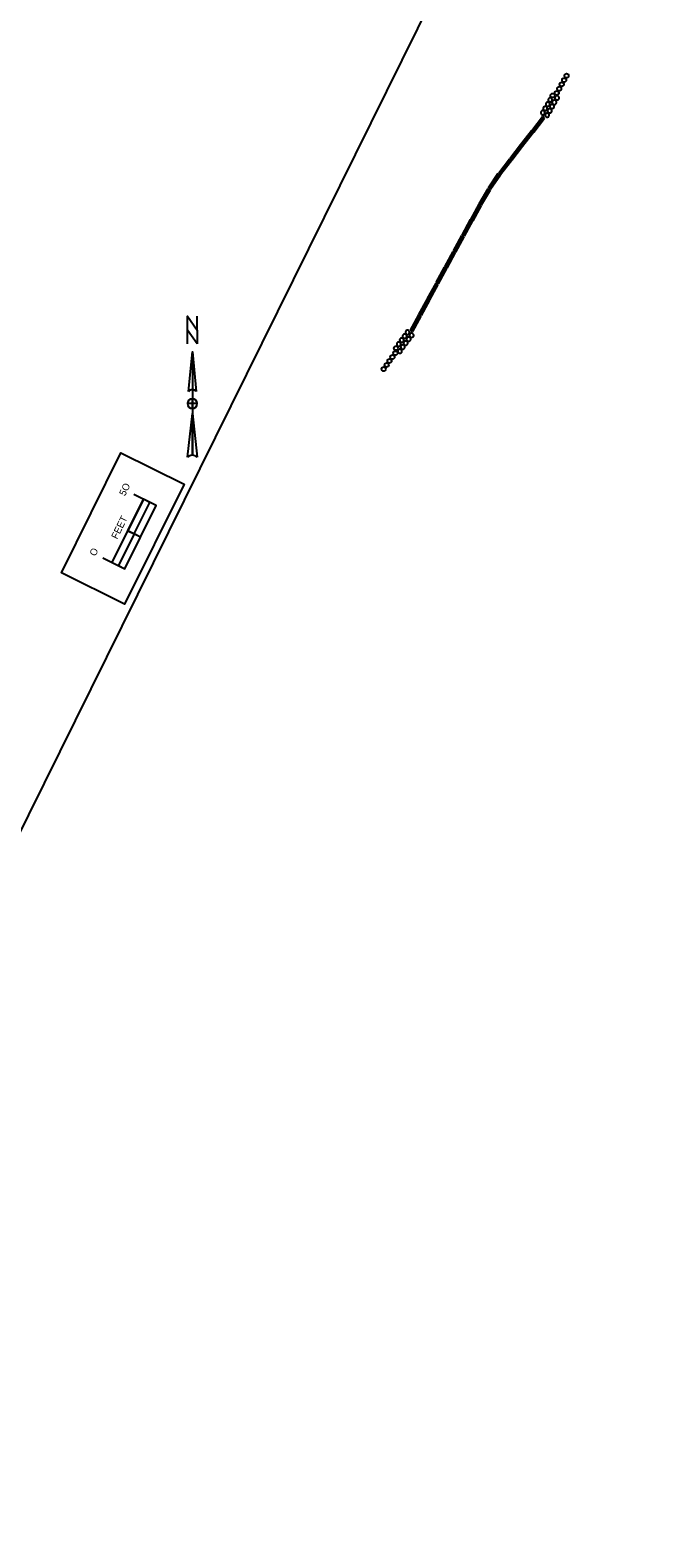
# Model space of a CAD drawing. Extents: x 14104283 to 14120882, y 8635219 to 8671666.
# Drawn here: x 14119252 to 14119692, y 8667406 to 8668475 of the extents above; entities that cross this region are included whole.
import ezdxf

# ---------------------------------------------------------------- set-up
doc = ezdxf.new("R2010")
doc.units = 0
for name, color, linetype in [('DisCLMLORPoints', 7, 'Continuous'), ('dsnBarrierTempUnpinned', 7, 'Continuous'), ('dsnCellsNorthArrow', 7, 'Continuous'), ('dsnCellsScaleBlock', 7, 'Continuous'), ('dsnNonPlotable', 7, 'Continuous')]:
    doc.layers.add(name, color=color, linetype=linetype)

msp = doc.modelspace()

# ---------------------------------------------------------------- linework, layer by layer
at = {"layer": 'DisCLMLORPoints'}
for centre in [(14119630.7, 8668439.8), (14119632.4, 8668442.9), (14119622.5, 8668428.9), (14119622.5, 8668428.9), (14119625.5, 8668430.7), (14119627.2, 8668433.7), (14119629, 8668436.8), (14119511.1, 8668246.2), (14119511.5, 8668249.7), (14119511.5, 8668249.7), (14119504.9, 8668237.8), (14119506.9, 8668240.6), (14119509, 8668243.4), (14119502.8, 8668234.9)]:
    msp.add_circle(centre, 1.5, dxfattribs=at)
for centre, start, end in [((14119617.3, 8668419.7), 55.5784, 235.5784), ((14119617.3, 8668419.7), 235.5784, 55.5784), ((14119619.1, 8668422.8), 55.5784, 235.5784), ((14119619.1, 8668422.8), 235.5784, 55.5784), ((14119620.4, 8668418), 55.5784, 235.5784), ((14119620.8, 8668425.8), 55.5784, 235.5784), ((14119620.4, 8668418), 235.5784, 55.5784), ((14119620.8, 8668425.8), 235.5784, 55.5784), ((14119622.1, 8668421.1), 55.5784, 235.5784), ((14119622.1, 8668421.1), 235.5784, 55.5784), ((14119623.8, 8668424.1), 55.5784, 235.5784), ((14119623.8, 8668424.1), 235.5784, 55.5784), ((14119625.6, 8668427.2), 55.5784, 235.5784), ((14119625.6, 8668427.2), 235.5784, 55.5784), ((14119615.6, 8668416.7), 55.5784, 235.5784), ((14119615.6, 8668416.7), 235.5784, 55.5784), ((14119618.7, 8668415), 55.5784, 235.5784), ((14119618.7, 8668415), 235.5784, 55.5784), ((14119517.7, 8668258.2), 58.7363, 238.7363), ((14119517.7, 8668258.2), 238.7363, 58.7363), ((14119519.7, 8668261), 58.7363, 238.7363), ((14119519.7, 8668261), 238.7363, 58.7363), ((14119522.6, 8668258.9), 58.7363, 238.7363), ((14119522.6, 8668258.9), 238.7363, 58.7363), ((14119513.5, 8668252.5), 58.7363, 238.7363), ((14119513.5, 8668252.5), 238.7363, 58.7363), ((14119514.3, 8668247.6), 58.7363, 238.7363), ((14119514.3, 8668247.6), 238.7363, 58.7363), ((14119515.6, 8668255.4), 58.7363, 238.7363), ((14119515.6, 8668255.4), 238.7363, 58.7363), ((14119516.3, 8668250.5), 58.7363, 238.7363), ((14119516.3, 8668250.5), 238.7363, 58.7363), ((14119518.4, 8668253.3), 58.7363, 238.7363), ((14119518.4, 8668253.3), 238.7363, 58.7363), ((14119520.5, 8668256.1), 58.7363, 238.7363), ((14119520.5, 8668256.1), 238.7363, 58.7363)]:
    msp.add_arc(centre, 1.5, start, end, dxfattribs=at)
at = {"layer": 'dsnBarrierTempUnpinned'}
for p, q in [((14119607.7, 8668404.2), (14119615.4, 8668414.1)), ((14119608.1, 8668403.8), (14119615.8, 8668413.7)), ((14119608.7, 8668403.4), (14119616.4, 8668413.3)), ((14119609.2, 8668403), (14119616.8, 8668412.9)), ((14119616.8, 8668412.9), (14119615.4, 8668414.1)), ((14119599.8, 8668394.1), (14119607.5, 8668404)), ((14119600.3, 8668393.7), (14119608, 8668403.6)), ((14119600.8, 8668393.3), (14119608.5, 8668403.2)), ((14119601.3, 8668392.9), (14119609, 8668402.8)), ((14119609, 8668402.8), (14119607.5, 8668404)), ((14119609.2, 8668403), (14119607.7, 8668404.2)), ((14119592.1, 8668384.2), (14119599.8, 8668394.1)), ((14119592.6, 8668383.9), (14119600.3, 8668393.7)), ((14119593.1, 8668383.4), (14119600.8, 8668393.3)), ((14119593.6, 8668383.1), (14119601.3, 8668392.9)), ((14119599.8, 8668394.1), (14119601.3, 8668392.9)), ((14119601.3, 8668392.9), (14119599.8, 8668394.1)), ((14119584.3, 8668374.1), (14119591.9, 8668384)), ((14119584.7, 8668373.7), (14119592.4, 8668383.6)), ((14119585.3, 8668373.3), (14119592.9, 8668383.2)), ((14119585.7, 8668373), (14119593.4, 8668382.8)), ((14119591.9, 8668384), (14119593.4, 8668382.8)), ((14119592.1, 8668384.2), (14119593.6, 8668383.1)), ((14119577, 8668363.4), (14119584, 8668373.8)), ((14119577.5, 8668363.1), (14119584.5, 8668373.4)), ((14119578.1, 8668362.7), (14119585.1, 8668373)), ((14119578.6, 8668362.4), (14119585.6, 8668372.7)), ((14119584, 8668373.8), (14119585.6, 8668372.7)), ((14119584.3, 8668374.1), (14119585.7, 8668373)), ((14119570.5, 8668352.2), (14119576.8, 8668363)), ((14119571, 8668351.9), (14119577.3, 8668362.7)), ((14119571.6, 8668351.6), (14119577.9, 8668362.4)), ((14119572.1, 8668351.3), (14119578.4, 8668362.1)), ((14119576.8, 8668363), (14119578.4, 8668362.1)), ((14119577, 8668363.4), (14119578.6, 8668362.4)), ((14119570.3, 8668351.9), (14119564.3, 8668340.9)), ((14119570.8, 8668351.6), (14119564.8, 8668340.6)), ((14119571.4, 8668351.3), (14119565.4, 8668340.3)), ((14119571.9, 8668351), (14119566, 8668340)), ((14119571.9, 8668351), (14119570.3, 8668351.9)), ((14119570.5, 8668352.2), (14119572.1, 8668351.3)), ((14119558.4, 8668329.9), (14119564.3, 8668340.9)), ((14119558.9, 8668329.7), (14119564.8, 8668340.6)), ((14119559.5, 8668329.3), (14119565.4, 8668340.3)), ((14119560, 8668329.1), (14119566, 8668340)), ((14119566, 8668340), (14119564.3, 8668340.9)), ((14119566, 8668340), (14119564.3, 8668340.9)), ((14119552.2, 8668318.7), (14119558.2, 8668329.7)), ((14119552.8, 8668318.4), (14119558.7, 8668329.4)), ((14119553.4, 8668318.1), (14119559.3, 8668329.1)), ((14119553.9, 8668317.8), (14119559.9, 8668328.8)), ((14119559.9, 8668328.8), (14119558.2, 8668329.7)), ((14119560, 8668329.1), (14119558.4, 8668329.9)), ((14119546.1, 8668307.4), (14119552.1, 8668318.4)), ((14119546.7, 8668307.2), (14119552.6, 8668318.1)), ((14119547.3, 8668306.8), (14119553.2, 8668317.8)), ((14119547.8, 8668306.5), (14119553.8, 8668317.5)), ((14119553.8, 8668317.5), (14119552.1, 8668318.4)), ((14119553.9, 8668317.8), (14119552.2, 8668318.7)), ((14119540, 8668296.2), (14119546, 8668307.2)), ((14119540.6, 8668295.9), (14119546.5, 8668306.9)), ((14119541.2, 8668295.6), (14119547.1, 8668306.6)), ((14119541.7, 8668295.3), (14119547.6, 8668306.3)), ((14119547.6, 8668306.3), (14119546, 8668307.2)), ((14119547.8, 8668306.5), (14119546.1, 8668307.4)), ((14119533.9, 8668284.9), (14119539.9, 8668295.9)), ((14119534.4, 8668284.7), (14119540.4, 8668295.6)), ((14119535, 8668284.3), (14119541, 8668295.3)), ((14119535.6, 8668284), (14119541.5, 8668295)), ((14119541.5, 8668295), (14119539.9, 8668295.9)), ((14119541.7, 8668295.3), (14119540, 8668296.2)), ((14119527.8, 8668273.7), (14119533.8, 8668284.7)), ((14119528.3, 8668273.4), (14119534.3, 8668284.4)), ((14119528.9, 8668273.1), (14119534.9, 8668284.1)), ((14119529.5, 8668272.8), (14119535.4, 8668283.8)), ((14119535.4, 8668283.8), (14119533.8, 8668284.7)), ((14119535.6, 8668284), (14119533.9, 8668284.9)), ((14119521.7, 8668262.4), (14119527.7, 8668273.4)), ((14119522.2, 8668262.2), (14119528.2, 8668273.1)), ((14119522.8, 8668261.8), (14119528.8, 8668272.8)), ((14119523.4, 8668261.5), (14119529.3, 8668272.5)), ((14119529.3, 8668272.5), (14119527.7, 8668273.4)), ((14119529.5, 8668272.8), (14119527.8, 8668273.7)), ((14119523.4, 8668261.5), (14119521.7, 8668262.4))]:
    msp.add_line(p, q, dxfattribs=at)
for centre in [(14119616.2, 8668413.6), (14119608.3, 8668403.5), (14119608.3, 8668403.5), (14119600.5, 8668393.4), (14119565.2, 8668340.6), (14119559.1, 8668329.4), (14119559.1, 8668329.4), (14119553, 8668318.1), (14119553, 8668318.1), (14119546.9, 8668306.9), (14119546.9, 8668306.9), (14119540.8, 8668295.6), (14119540.8, 8668295.6), (14119534.7, 8668284.4), (14119534.7, 8668284.4), (14119528.6, 8668273.1), (14119528.6, 8668273.1), (14119522.5, 8668261.9)]:
    msp.add_circle(centre, 0.0521, dxfattribs=at)
for centre, start, end in [((14119616.1, 8668413.5), 322.103, 142.103), ((14119608.2, 8668403.4), 322.103, 142.103), ((14119608.4, 8668403.6), 142.103, 322.103), ((14119600.6, 8668393.5), 142.103, 322.103), ((14119565.1, 8668340.5), 331.499, 151.499), ((14119559, 8668329.2), 331.499, 151.499), ((14119559.2, 8668329.5), 151.499, 331.499), ((14119552.9, 8668318), 331.499, 151.499), ((14119553.1, 8668318.2), 151.499, 331.499), ((14119546.8, 8668306.7), 331.499, 151.499), ((14119547, 8668307), 151.499, 331.499), ((14119540.7, 8668295.5), 331.499, 151.499), ((14119540.9, 8668295.7), 151.499, 331.499), ((14119534.6, 8668284.2), 331.499, 151.499), ((14119534.7, 8668284.5), 151.499, 331.499), ((14119528.5, 8668273), 331.499, 151.499), ((14119528.6, 8668273.2), 151.499, 331.499), ((14119522.5, 8668262), 151.499, 331.499)]:
    msp.add_arc(centre, 0.281, start, end, dxfattribs=at)
at = {"layer": 'dsnCellsNorthArrow'}
for p, q in [((14119367.2, 8668247.1), (14119370, 8668218.9)), ((14119367.2, 8668247.1), (14119367.2, 8668173.8)), ((14119364.4, 8668218.9), (14119364.4, 8668218.9)), ((14119364.5, 8668219.1), (14119365, 8668219.7)), ((14119367.2, 8668206.9), (14119367.2, 8668206.9)), ((14119363.7, 8668172.4), (14119367.2, 8668203.4))]:
    msp.add_line(p, q, dxfattribs=at)
msp.add_lwpolyline([(14119370.7, 8668252.7), (14119363.7, 8668262.6), (14119363.7, 8668272.4), (14119370.7, 8668262.6)], close=True, dxfattribs=at)
for points in [[(14119363.7, 8668252.7), (14119363.7, 8668272.4), (14119370.7, 8668262.6), (14119370.7, 8668272.4)], [(14119364.4, 8668218.9), (14119367.2, 8668247.1), (14119367.2, 8668220.3)], [(14119367.2, 8668206.9), (14119367.2, 8668210.4), (14119363.7, 8668210.4)], [(14119370.7, 8668210.4), (14119367.2, 8668210.4), (14119367.2, 8668214)], [(14119367.2, 8668173.8), (14119367.2, 8668203.4), (14119370.7, 8668172.4)]]:
    msp.add_lwpolyline(points, dxfattribs=at)
for centre, radius, start, end in [((14119367.2, 8668216.8), 3.52, 90.0204, 143.1257), ((14119367.2, 8668216.8), 3.52, 36.8481, 90.0218), ((14119367.2, 8668210.4), 3.52, 90, 180), ((14119367.2, 8668210.4), 3.52, 180, 270), ((14119367.2, 8668210.4), 3.52, 0, 90), ((14119367.2, 8668210.4), 3.52, 270, 360), ((14119367.2, 8668168.7), 5.1, 89.9894, 133.619), ((14119367.2, 8668168.7), 5.11, 46.4021, 90.0006)]:
    msp.add_arc(centre, radius, start, end, dxfattribs=at)
at = {"layer": 'dsnCellsScaleBlock'}
msp.add_line((14119330.4, 8668115.7), (14119321.5, 8668120.2), dxfattribs=at)
msp.add_line((14119330.4, 8668115.7), (14119321.5, 8668120.2), dxfattribs=at)
for points in [[(14119274.4, 8668090.4), (14119316.5, 8668175.6), (14119361.3, 8668153.4), (14119319.2, 8668068.3)], [(14119319.2, 8668068.3), (14119274.4, 8668090.4), (14119316.5, 8668175.6), (14119361.3, 8668153.4)], [(14119325.9, 8668118), (14119337, 8668140.4), (14119332.6, 8668142.6), (14119321.5, 8668120.2)], [(14119319.4, 8668093.3), (14119330.4, 8668115.7), (14119325.9, 8668118), (14119314.8, 8668095.5)]]:
    msp.add_lwpolyline(points, close=True, dxfattribs=at)
for points in [[(14119303.7, 8668101.1), (14119319.4, 8668093.3), (14119341.5, 8668138.1), (14119325.8, 8668145.9)], [(14119310.4, 8668097.7), (14119332.6, 8668142.6)]]:
    msp.add_lwpolyline(points, dxfattribs=at)
at = {"layer": 'dsnNonPlotable'}
msp.add_lwpolyline([(14118092, 8667853.7), (14118786.8, 8669258.8), (14119692.1, 8668811.2), (14118997.4, 8667406.1)], close=True, dxfattribs=at)

# ---------------------------------------------------------------- texts
at = {"layer": 'dsnCellsScaleBlock'}
for s, p in [('5O', (14119319.5, 8668144.5)), ('FEET', (14119313.9, 8668113.9)), ('O', (14119298.5, 8668101.8))]:
    msp.add_text(s, height=5, rotation=63.6912, dxfattribs=at).set_placement(p)

doc.saveas('drawing.dxf')
